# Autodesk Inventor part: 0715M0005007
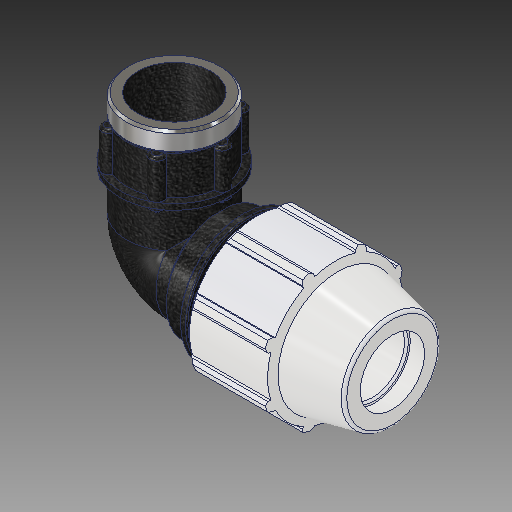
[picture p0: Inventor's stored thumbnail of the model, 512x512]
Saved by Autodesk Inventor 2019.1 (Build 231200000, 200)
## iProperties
Created: 2017-02
Part Number: 0715M0005007
Material: PVC-Piping
Description: PLASSON 90° ELBOW FEMALE ADAPTOR 1/2'' - 3/4''F
Document SubType Name: Modeling
Designer: KIM
Mass: 92.6774 g
Surface Area: 199.44 cm^2
Volume: 66.1981 cm^3
Density: 1.4 g/cm^3
Appearance: PTFE
Author: KIM
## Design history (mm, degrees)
derived "0715M0.ipt"
feature "Solid1::0715M0.ipt"
tag "TaggingFeature1"
body "Solid1"
other parameters: "d_" = 21.2, "E_" = 48.006, "A_" = 71.882, "l_" = 52.07, "l_2" = 19.05, "A_1" = 43.942, "G_" = 24.117, "d105" = 4.70281, "d2" = 21.2, "d4" = 5.99017, "d5" = 17.9705, "d7" = 48.006, "d9" = 10.26886, "d11" = 2.39607, "d13" = 120 deg, "d14" = 31.8, "d15" = 12 deg, "d16" = 41.76522, "d18" = 1.06, "d19" = 35 deg, "d20" = 17.5 deg, "d21" = 44.64558, "d23" = 0, "d25" = 360 deg, "d27" = 0.96012, "d33" = 0.424, "d42" = 26.59634, "d43" = 1.44018, "d46" = 0.636, "d51" = 71.882, "d68" = 2.39607, "d72" = 43.942, "d73" = 31.3521, "d74" = 19.05, "d75" = 36.05492, "d76" = 24.117, "d77" = 20.955, "d79" = 9.6468, "d80" = 0.72351, "d83" = 0, "d84" = 0, "d91" = 36.0045, "d93" = 52.07, "d94" = 24.117, "d95" = 16.8819, "d96" = 7.1882, "d97" = 50 deg, "d98" = 21.7053, "d99" = 0.5, "d100" = 0.5, "d101" = 6.35, "d102" = 31.3521, "d103" = 16.1925, "d104" = 0, "d108" = 360 deg, "d110" = 0.94056
